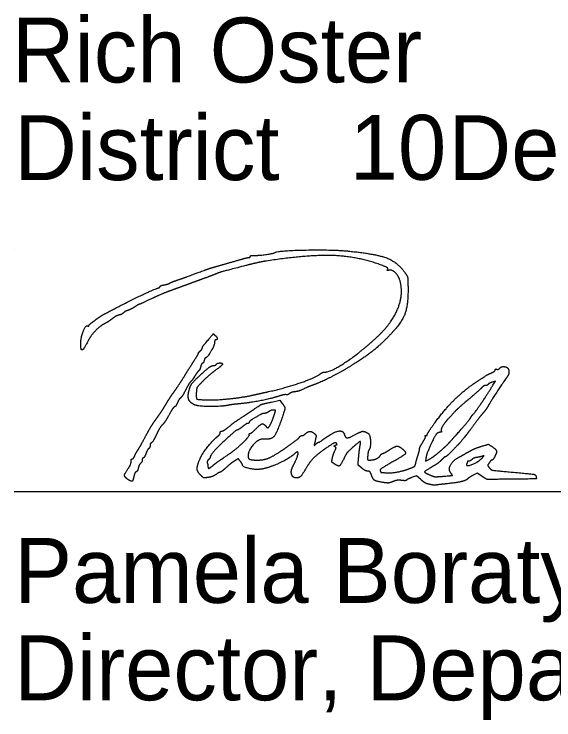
# Model space of a CAD drawing. Extents: x 0 to 34, y 0 to 22.
# Drawn here: x 24.528 to 25.691, y 7.242 to 8.764 of the extents above; entities that cross this region are included whole.
import ezdxf

# ---------------------------------------------------------------- set-up
doc = ezdxf.new("R2010")
doc.units = 0
for name, color, linetype in [('Default', 7, 'Continuous'), ('SH_Data', 7, 'Continuous'), ('SH_Text', 7, 'Continuous')]:
    doc.layers.add(name, color=color, linetype=linetype)

msp = doc.modelspace()

# ---------------------------------------------------------------- linework, layer by layer
at = {"layer": 'Default'}
for points in [[(25.5597, 7.9636), (25.5651, 7.9726), (25.5577, 7.97)], [(25.0824, 7.9275), (25.1004, 7.9315), (25.1051, 7.9253)], [(25.2773, 7.7846), (25.269, 7.791), (25.2704, 7.808)], [(25.4153, 7.8066), (25.4143, 7.8002), (25.4229, 7.8046)], [(25.4043, 7.7603), (25.3951, 7.7686), (25.3845, 7.7645)], [(25.5361, 7.7673), (25.5255, 7.7741), (25.5171, 7.7696)]]:
    msp.add_lwpolyline(points, dxfattribs=at)
for points in [[(25.0898, 8.25), (25.0966, 8.2542), (25.2136, 8.2565), (25.248, 8.2531)], [(25.248, 8.2531), (25.3072, 8.2473), (25.3548, 8.229), (25.3706, 8.206)], [(25, 8.2304), (25.0161, 8.2352), (25.031, 8.2391), (25.033, 8.2391)], [(25.033, 8.2391), (25.0351, 8.2391), (25.0368, 8.2402), (25.0368, 8.2416)], [(25.0368, 8.2416), (25.0368, 8.243), (25.0408, 8.244), (25.0458, 8.2438)], [(25.0458, 8.2438), (25.0554, 8.2435), (25.0864, 8.2479), (25.0898, 8.25)], [(25.3205, 8.2224), (25.2699, 8.2414), (25.1619, 8.2454), (25.0716, 8.2316)], [(24.9612, 8.2193), (24.9665, 8.2207), (24.9839, 8.2257), (25, 8.2304)], [(25.0272, 8.2219), (24.9762, 8.2087), (24.9719, 8.2075), (24.9612, 8.2031)], [(25.0716, 8.2316), (25.0623, 8.2302), (25.0424, 8.2258), (25.0272, 8.2219)], [(25.3328, 8.2137), (25.3338, 8.2163), (25.3303, 8.2187), (25.3205, 8.2224)], [(24.8808, 8.1909), (24.8955, 8.196), (24.9019, 8.1983), (24.9372, 8.2115)], [(24.9372, 8.2115), (24.9451, 8.2144), (24.9559, 8.2179), (24.9612, 8.2193)], [(25.3352, 8.2117), (25.3326, 8.2107), (25.3319, 8.2113), (25.3328, 8.2137)], [(25.3586, 8.1918), (25.3553, 8.2015), (25.3409, 8.2139), (25.3352, 8.2117)], [(25.3706, 8.206), (25.3755, 8.1987), (25.3764, 8.1944), (25.3768, 8.1765)], [(24.8628, 8.1837), (24.8641, 8.1847), (24.8722, 8.1879), (24.8808, 8.1909)], [(24.9384, 8.1946), (24.9285, 8.191), (24.9134, 8.1854), (24.9048, 8.1822)], [(24.9612, 8.2031), (24.9585, 8.202), (24.9483, 8.1982), (24.9384, 8.1946)], [(25.3131, 8.0706), (25.344, 8.1), (25.3679, 8.1635), (25.3586, 8.1918)], [(24.837, 8.173), (24.84, 8.1739), (24.8424, 8.1755), (24.8424, 8.1766)], [(24.8424, 8.1766), (24.8424, 8.1777), (24.8464, 8.1793), (24.8514, 8.1802)], [(24.8514, 8.1802), (24.8563, 8.1812), (24.8615, 8.1827), (24.8628, 8.1837)], [(24.9048, 8.1822), (24.8962, 8.179), (24.88, 8.1731), (24.8688, 8.1691)], [(25.3768, 8.1765), (25.3775, 8.1357), (25.3614, 8.096), (25.332, 8.0661)], [(24.7248, 8.1187), (24.755, 8.1349), (24.8286, 8.1706), (24.837, 8.173)], [(24.8688, 8.1691), (24.8576, 8.1651), (24.8372, 8.1565), (24.8236, 8.1501)], [(24.8236, 8.1501), (24.8099, 8.1436), (24.7983, 8.1383), (24.7977, 8.1383)], [(24.7877, 8.1327), (24.7828, 8.1295), (24.7761, 8.1262), (24.7729, 8.1251)], [(24.7977, 8.1383), (24.7971, 8.1383), (24.7927, 8.1358), (24.7877, 8.1327)], [(24.6888, 8.0921), (24.6888, 8.0942), (24.7142, 8.113), (24.7248, 8.1187)], [(24.754, 8.1151), (24.7505, 8.1143), (24.7438, 8.1107), (24.7392, 8.1071)], [(24.7637, 8.12), (24.7619, 8.1182), (24.7576, 8.116), (24.754, 8.1151)], [(24.7729, 8.1251), (24.7697, 8.1241), (24.7655, 8.1218), (24.7637, 8.12)], [(24.7392, 8.1071), (24.7346, 8.1035), (24.7274, 8.0988), (24.7233, 8.0967)], [(24.6716, 8.0542), (24.6717, 8.0674), (24.6823, 8.094), (24.6865, 8.0914)], [(24.6865, 8.0914), (24.6877, 8.0907), (24.6888, 8.0909), (24.6888, 8.0921)], [(24.7233, 8.0967), (24.7129, 8.0914), (24.693, 8.0705), (24.6868, 8.0584)], [(24.939, 8.0531), (24.9575, 8.0753), (24.9568, 8.0747), (24.9609, 8.0713)], [(24.9609, 8.0713), (24.9652, 8.0678), (24.9661, 8.0615), (24.9624, 8.0615)], [(25.1964, 7.9919), (25.2105, 7.9919), (25.2786, 8.0378), (25.3131, 8.0706)], [(24.673, 8.0405), (24.6722, 8.0413), (24.6716, 8.0475), (24.6716, 8.0542)], [(24.6868, 8.0584), (24.6801, 8.0455), (24.6748, 8.0386), (24.673, 8.0405)], [(24.9336, 8.0445), (24.9336, 8.0457), (24.936, 8.0496), (24.939, 8.0531)], [(24.96, 8.0564), (24.96, 8.0509), (24.9441, 8.0231), (24.9409, 8.0231)], [(24.9624, 8.0615), (24.9611, 8.0615), (24.96, 8.0592), (24.96, 8.0564)], [(25.332, 8.0661), (25.3134, 8.0472), (25.281, 8.0223), (25.2505, 8.0035)], [(24.9288, 8.0375), (24.9314, 8.0401), (24.9336, 8.0433), (24.9336, 8.0445)], [(24.916, 8.017), (24.9216, 8.0257), (24.9256, 8.0327), (24.925, 8.0327)], [(24.925, 8.0327), (24.9245, 8.0327), (24.9261, 8.0349), (24.9288, 8.0375)], [(24.9409, 8.0231), (24.9398, 8.0231), (24.9382, 8.0204), (24.9374, 8.0171)], [(24.894, 7.982), (24.9006, 7.9927), (24.9105, 8.0084), (24.916, 8.017)], [(24.9337, 8.0111), (24.9325, 8.0111), (24.9309, 8.0079), (24.93, 8.0039)], [(24.9374, 8.0171), (24.9366, 8.0138), (24.9349, 8.0111), (24.9337, 8.0111)], [(24.9576, 8.0063), (24.9601, 8.0063), (24.9628, 8.0074), (24.9636, 8.0087)], [(24.9768, 8.0091), (24.9768, 8.008), (24.97, 8.002), (24.9618, 7.9959)], [(24.9636, 8.0087), (24.9654, 8.0116), (24.9768, 8.0119), (24.9768, 8.0091)], [(24.9261, 7.9953), (24.9248, 7.9945), (24.921, 7.9894), (24.9176, 7.9839)], [(24.9252, 7.9821), (24.9409, 7.9968), (24.9536, 8.0063), (24.9576, 8.0063)], [(24.93, 8.0039), (24.9291, 8), (24.9274, 7.9961), (24.9261, 7.9953)], [(24.9618, 7.9959), (24.9535, 7.9898), (24.941, 7.979), (24.934, 7.9718)], [(25.2505, 8.0035), (25.2313, 7.9917), (25.1901, 7.9707), (25.176, 7.9656)], [(25.557, 7.9905), (25.5613, 7.9925), (25.5648, 7.9953), (25.5648, 7.9968)], [(25.5648, 7.9968), (25.5648, 7.9984), (25.5663, 7.999), (25.5682, 7.9983)], [(25.5682, 7.9983), (25.5701, 7.9976), (25.5729, 7.9985), (25.5745, 8.0004)], [(25.5745, 8.0004), (25.5761, 8.0023), (25.5798, 8.0039), (25.5827, 8.0039)], [(25.5827, 8.0039), (25.5921, 8.0039), (25.5959, 7.9879), (25.5885, 7.9789)], [(24.8722, 7.9491), (24.8776, 7.9566), (24.8874, 7.9714), (24.894, 7.982)], [(24.9038, 7.9475), (24.9066, 7.9605), (24.9127, 7.9705), (24.9252, 7.9821)], [(24.9176, 7.9839), (24.9142, 7.9784), (24.9101, 7.9728), (24.9084, 7.9715)], [(25.0764, 7.95), (25.1133, 7.9582), (25.1796, 7.9811), (25.1882, 7.9886)], [(25.1882, 7.9886), (25.1903, 7.9904), (25.1939, 7.9919), (25.1964, 7.9919)], [(25.528, 7.9735), (25.5469, 7.9858), (25.5488, 7.9869), (25.557, 7.9905)], [(25.5885, 7.9789), (25.5843, 7.9739), (25.5515, 7.9234), (25.5483, 7.9172)], [(24.9084, 7.9715), (24.9068, 7.9701), (24.9021, 7.9625), (24.8981, 7.9545)], [(24.934, 7.9718), (24.9233, 7.9609), (24.9211, 7.9572), (24.9206, 7.949)], [(25.176, 7.9656), (25.1714, 7.9639), (25.1643, 7.9611), (25.1603, 7.9594)], [(25.4334, 7.881), (25.4556, 7.9118), (25.5007, 7.9558), (25.528, 7.9735)], [(25.5169, 7.9007), (25.5197, 7.9027), (25.5479, 7.9441), (25.5597, 7.9636)], [(25.5437, 7.9631), (25.5415, 7.9631), (25.5375, 7.9607), (25.5349, 7.9577)], [(25.549, 7.9653), (25.5483, 7.9641), (25.5459, 7.9631), (25.5437, 7.9631)], [(25.5577, 7.97), (25.5537, 7.9686), (25.5498, 7.9665), (25.549, 7.9653)], [(24.8555, 7.9235), (24.8593, 7.9301), (24.8669, 7.9416), (24.8722, 7.9491)], [(24.8981, 7.9545), (24.8941, 7.9465), (24.889, 7.9385), (24.8868, 7.9367)], [(24.9192, 7.9207), (24.9087, 7.9246), (24.9016, 7.937), (24.9038, 7.9475)], [(24.9206, 7.949), (24.9197, 7.9355), (24.9238, 7.9326), (24.9444, 7.9321)], [(25.0428, 7.9425), (25.0507, 7.9443), (25.0658, 7.9476), (25.0764, 7.95)], [(25.1318, 7.9495), (25.1279, 7.949), (25.123, 7.9472), (25.121, 7.9454)], [(25.1603, 7.9594), (25.1433, 7.9519), (25.1384, 7.9502), (25.1318, 7.9495)], [(25.5349, 7.9577), (25.5322, 7.9547), (25.5197, 7.9437), (25.5072, 7.9331)], [(24.8868, 7.9367), (24.8847, 7.935), (24.8814, 7.9299), (24.8796, 7.9255)], [(24.9444, 7.9321), (24.9636, 7.9316), (25.0215, 7.9377), (25.0428, 7.9425)], [(25.0962, 7.9395), (25.0797, 7.9342), (25.0346, 7.9257), (25.0108, 7.9234)], [(25.1142, 7.9432), (25.1125, 7.9438), (25.1044, 7.9421), (25.0962, 7.9395)], [(25.121, 7.9454), (25.1189, 7.9436), (25.1158, 7.9426), (25.1142, 7.9432)], [(25.5072, 7.9331), (25.4876, 7.9166), (25.4759, 7.9052), (25.4592, 7.8863)], [(24.8425, 7.9029), (24.8458, 7.9076), (24.8517, 7.9169), (24.8555, 7.9235)], [(24.8739, 7.9175), (24.8726, 7.9175), (24.8672, 7.9096), (24.8618, 7.8999)], [(24.8796, 7.9255), (24.8777, 7.9211), (24.8752, 7.9175), (24.8739, 7.9175)], [(24.9904, 7.9208), (24.9767, 7.9178), (24.9272, 7.9177), (24.9192, 7.9207)], [(25.0108, 7.9234), (25.0025, 7.9226), (24.9933, 7.9214), (24.9904, 7.9208)], [(25.0284, 7.901), (25.06, 7.9221), (25.0614, 7.9228), (25.0824, 7.9275)], [(25.1051, 7.9253), (25.1117, 7.9166), (25.1115, 7.9117), (25.1038, 7.8891)], [(25.5483, 7.9172), (25.5466, 7.9138), (25.5427, 7.9083), (25.5397, 7.9051)], [(24.8289, 7.8837), (24.833, 7.8895), (24.8391, 7.8981), (24.8425, 7.9029)], [(24.9892, 7.8731), (25.0029, 7.8842), (25.0009, 7.8828), (25.0284, 7.901)], [(25.0678, 7.9031), (25.0656, 7.9031), (25.0612, 7.9017), (25.0581, 7.9)], [(25.0765, 7.9066), (25.074, 7.9047), (25.07, 7.9031), (25.0678, 7.9031)], [(25.075, 7.8719), (25.0768, 7.8719), (25.0866, 7.893), (25.0897, 7.9037)], [(25.0864, 7.9102), (25.0835, 7.9102), (25.0791, 7.9086), (25.0765, 7.9066)], [(25.0897, 7.9037), (25.0914, 7.9095), (25.091, 7.9103), (25.0864, 7.9102)], [(25.513, 7.8956), (25.5142, 7.8977), (25.5159, 7.9), (25.5169, 7.9007)], [(25.5397, 7.9051), (25.5367, 7.9019), (25.5278, 7.8905), (25.5199, 7.8799)], [(24.8618, 7.8999), (24.8565, 7.8903), (24.8498, 7.8803), (24.847, 7.8777)], [(25.0581, 7.9), (25.0436, 7.892), (25.0344, 7.8856), (25.0344, 7.8837)], [(25.1038, 7.8891), (25.0935, 7.8592), (25.0815, 7.8462), (25.0656, 7.8475)], [(25.4592, 7.8863), (25.4533, 7.8797), (25.4471, 7.8668), (25.4485, 7.8645)], [(25.4817, 7.8577), (25.497, 7.8749), (25.5106, 7.8912), (25.513, 7.8956)], [(24.81, 7.8515), (24.8163, 7.8634), (24.8248, 7.8779), (24.8289, 7.8837)], [(24.847, 7.8777), (24.8441, 7.8752), (24.8386, 7.8661), (24.8347, 7.8575)], [(24.9754, 7.8647), (24.9772, 7.8647), (24.9834, 7.8685), (24.9892, 7.8731)], [(25.02, 7.8743), (25.015, 7.8703), (25.01, 7.8671), (25.0088, 7.8671)], [(25.0317, 7.8815), (25.0303, 7.8815), (25.025, 7.8783), (25.02, 7.8743)], [(25.0344, 7.8837), (25.0344, 7.8825), (25.0332, 7.8815), (25.0317, 7.8815)], [(25.0488, 7.8695), (25.0589, 7.8796), (25.0654, 7.8814), (25.0704, 7.8755)], [(25.0704, 7.8755), (25.072, 7.8735), (25.0741, 7.8719), (25.075, 7.8719)], [(25.4184, 7.8577), (25.4184, 7.8591), (25.4251, 7.8696), (25.4334, 7.881)], [(25.5199, 7.8799), (25.512, 7.8692), (25.5043, 7.859), (25.5029, 7.8572)], [(24.8347, 7.8575), (24.8307, 7.8489), (24.826, 7.841), (24.8242, 7.84)], [(24.9666, 7.8535), (24.9695, 7.8559), (24.972, 7.8594), (24.972, 7.8613)], [(24.972, 7.8613), (24.972, 7.8632), (24.9735, 7.8647), (24.9754, 7.8647)], [(25.0088, 7.8671), (25.0069, 7.8671), (24.9985, 7.8598), (24.9732, 7.8366)], [(24.9883, 7.8133), (25.0039, 7.8237), (25.0344, 7.8525), (25.0344, 7.8568)], [(25.0344, 7.8568), (25.0344, 7.8585), (25.0355, 7.8599), (25.0368, 7.8599)], [(25.0368, 7.8599), (25.0381, 7.8599), (25.0435, 7.8642), (25.0488, 7.8695)], [(25.1431, 7.852), (25.1442, 7.8537), (25.1465, 7.8551), (25.1483, 7.8551)], [(25.1483, 7.8551), (25.1501, 7.8551), (25.1534, 7.8569), (25.1555, 7.859)], [(25.1555, 7.859), (25.1605, 7.864), (25.1705, 7.864), (25.1754, 7.8591)], [(25.1754, 7.8591), (25.1786, 7.8559), (25.1788, 7.8534), (25.1767, 7.8443)], [(25.1935, 7.8464), (25.2138, 7.8616), (25.2365, 7.8672), (25.2395, 7.8578)], [(25.2395, 7.8578), (25.2419, 7.8502), (25.25, 7.8501), (25.2633, 7.8574)], [(25.2633, 7.8574), (25.2752, 7.864), (25.2825, 7.8647), (25.2907, 7.8601)], [(25.2907, 7.8601), (25.2951, 7.8577), (25.2967, 7.8297), (25.2928, 7.8245)], [(25.4142, 7.8537), (25.4134, 7.8545), (25.414, 7.8551), (25.4156, 7.8551)], [(25.4156, 7.8551), (25.4171, 7.8551), (25.4184, 7.8563), (25.4184, 7.8577)], [(25.4462, 7.8623), (25.4399, 7.8623), (25.4304, 7.8471), (25.4183, 7.8179)], [(25.4485, 7.8645), (25.4493, 7.8633), (25.4482, 7.8623), (25.4462, 7.8623)], [(25.4661, 7.8403), (25.4692, 7.8438), (25.4762, 7.8517), (25.4817, 7.8577)], [(25.5029, 7.8572), (25.4896, 7.8408), (25.485, 7.8356), (25.4732, 7.8235)], [(24.7946, 7.8239), (24.7968, 7.8272), (24.8037, 7.8396), (24.81, 7.8515)], [(24.8242, 7.84), (24.8223, 7.8389), (24.8208, 7.836), (24.8208, 7.8335)], [(24.9285, 7.8052), (24.933, 7.8157), (24.9562, 7.8451), (24.9666, 7.8535)], [(25.0656, 7.8475), (25.0552, 7.8484), (25.032, 7.823), (25.032, 7.8108)], [(25.1004, 7.8202), (25.119, 7.8326), (25.1414, 7.8493), (25.1431, 7.852)], [(25.1767, 7.8443), (25.1744, 7.834), (25.1745, 7.8336), (25.1783, 7.837)], [(25.1783, 7.837), (25.1805, 7.839), (25.1832, 7.8407), (25.1841, 7.8407)], [(25.1841, 7.8407), (25.1851, 7.8407), (25.1893, 7.8433), (25.1935, 7.8464)], [(25.2734, 7.8329), (25.2752, 7.8423), (25.2726, 7.8428), (25.2633, 7.8346)], [(25.4016, 7.826), (25.4016, 7.8279), (25.4047, 7.8345), (25.4086, 7.8408)], [(25.4086, 7.8408), (25.4125, 7.8471), (25.415, 7.8529), (25.4142, 7.8537)], [(25.446, 7.8214), (25.4539, 7.8283), (25.4629, 7.8367), (25.4661, 7.8403)], [(24.8183, 7.8274), (24.8169, 7.8266), (24.8141, 7.8217), (24.812, 7.8165)], [(24.8208, 7.8335), (24.8208, 7.831), (24.8197, 7.8283), (24.8183, 7.8274)], [(24.9732, 7.8366), (24.9641, 7.8282), (24.9504, 7.8111), (24.9504, 7.8081)], [(25.202, 7.8292), (25.1823, 7.8157), (25.1651, 7.7987), (25.1568, 7.7843)], [(25.2222, 7.8386), (25.2204, 7.8404), (25.2145, 7.8377), (25.202, 7.8292)], [(25.2194, 7.831), (25.2172, 7.8323), (25.2175, 7.8333), (25.2206, 7.8344)], [(25.2187, 7.8211), (25.2215, 7.8274), (25.2217, 7.8295), (25.2194, 7.831)], [(25.2206, 7.8344), (25.2236, 7.8356), (25.224, 7.8368), (25.2222, 7.8386)], [(25.2633, 7.8346), (25.2474, 7.8205), (25.2437, 7.8161), (25.2382, 7.8048)], [(25.2704, 7.808), (25.2712, 7.8174), (25.2726, 7.8286), (25.2734, 7.8329)], [(25.2928, 7.8245), (25.2916, 7.8228), (25.2903, 7.8172), (25.2899, 7.8119)], [(25.3642, 7.8269), (25.3739, 7.8193), (25.367, 7.8113), (25.3354, 7.7936)], [(25.336, 7.8239), (25.3489, 7.8321), (25.3565, 7.8329), (25.3642, 7.8269)], [(25.3981, 7.8119), (25.4, 7.8178), (25.4016, 7.8242), (25.4016, 7.826)], [(25.506, 7.8194), (25.5139, 7.824), (25.5271, 7.8297), (25.5353, 7.8321)], [(25.5353, 7.8321), (25.5493, 7.8363), (25.5505, 7.8364), (25.5564, 7.8325)], [(25.5564, 7.8325), (25.566, 7.8262), (25.5684, 7.8188), (25.5638, 7.8098)], [(24.7824, 7.8047), (24.7838, 7.8047), (24.7862, 7.8077), (24.7877, 7.8113)], [(24.7877, 7.8113), (24.7893, 7.8149), (24.7924, 7.8206), (24.7946, 7.8239)], [(24.812, 7.8165), (24.81, 7.8113), (24.8073, 7.8071), (24.8061, 7.8071)], [(24.9568, 7.791), (24.9643, 7.7971), (24.9696, 7.8008), (24.9883, 7.8133)], [(25.032, 7.8108), (25.032, 7.8056), (25.0398, 7.8023), (25.0519, 7.8023)], [(25.0519, 7.8023), (25.065, 7.8023), (25.0841, 7.8094), (25.1004, 7.8202)], [(25.1324, 7.8161), (25.1228, 7.8069), (25.084, 7.7881), (25.0656, 7.7837)], [(25.1294, 7.7903), (25.1335, 7.798), (25.14, 7.8143), (25.14, 7.817)], [(25.14, 7.817), (25.14, 7.8201), (25.136, 7.8196), (25.1324, 7.8161)], [(25.2136, 7.8055), (25.2144, 7.8097), (25.2166, 7.8167), (25.2187, 7.8211)], [(25.2899, 7.8119), (25.2894, 7.8043), (25.2901, 7.8023), (25.2932, 7.8023)], [(25.2932, 7.8023), (25.3016, 7.8023), (25.3136, 7.8071), (25.3168, 7.8118)], [(25.3168, 7.8118), (25.3187, 7.8145), (25.3212, 7.8167), (25.3224, 7.8167)], [(25.3224, 7.8167), (25.3236, 7.8167), (25.3297, 7.8199), (25.336, 7.8239)], [(25.3933, 7.7948), (25.394, 7.7983), (25.3961, 7.806), (25.3981, 7.8119)], [(25.4183, 7.8179), (25.4172, 7.8153), (25.4159, 7.8102), (25.4153, 7.8066)], [(25.4229, 7.8046), (25.4277, 7.807), (25.4381, 7.8146), (25.446, 7.8214)], [(25.4576, 7.8095), (25.4565, 7.8095), (25.4526, 7.8064), (25.449, 7.8025)], [(25.4732, 7.8235), (25.4657, 7.8158), (25.4586, 7.8095), (25.4576, 7.8095)], [(25.4864, 7.8084), (25.4893, 7.81), (25.4981, 7.8149), (25.506, 7.8194)], [(25.5372, 7.8107), (25.5345, 7.8098), (25.5292, 7.8085), (25.5254, 7.808)], [(25.5348, 7.8052), (25.5403, 7.8108), (25.5408, 7.8121), (25.5372, 7.8107)], [(25.5638, 7.8098), (25.5616, 7.8057), (25.5589, 7.8023), (25.5578, 7.8023)], [(24.7742, 7.7848), (24.7774, 7.7895), (24.78, 7.7959), (24.78, 7.799)], [(24.78, 7.799), (24.78, 7.8022), (24.7811, 7.8047), (24.7824, 7.8047)], [(24.8005, 7.7952), (24.7986, 7.7937), (24.7964, 7.7891), (24.7955, 7.7852)], [(24.804, 7.8026), (24.804, 7.8001), (24.8024, 7.7968), (24.8005, 7.7952)], [(24.8061, 7.8071), (24.8049, 7.8071), (24.804, 7.8051), (24.804, 7.8026)], [(24.9302, 7.7695), (24.9225, 7.7771), (24.9219, 7.79), (24.9285, 7.8052)], [(24.9466, 7.803), (24.9446, 7.801), (24.9435, 7.7977), (24.9442, 7.7958)], [(24.9442, 7.7958), (24.945, 7.7939), (24.9456, 7.7908), (24.9456, 7.7889)], [(24.9504, 7.8081), (24.9504, 7.8074), (24.9487, 7.8051), (24.9466, 7.803)], [(25.0041, 7.8011), (24.9959, 7.7957), (24.9933, 7.7937), (24.9821, 7.7837)], [(25.0154, 7.7997), (25.0109, 7.8055), (25.0108, 7.8056), (25.0041, 7.8011)], [(25.0199, 7.7924), (25.0199, 7.7932), (25.0179, 7.7965), (25.0154, 7.7997)], [(25.2182, 7.794), (25.2132, 7.7972), (25.2124, 7.7992), (25.2136, 7.8055)], [(25.2382, 7.8048), (25.2315, 7.7911), (25.2267, 7.7884), (25.2182, 7.794)], [(25.3806, 7.7842), (25.3894, 7.7876), (25.3923, 7.79), (25.3933, 7.7948)], [(25.449, 7.8025), (25.4454, 7.7987), (25.4373, 7.7926), (25.431, 7.789)], [(25.4694, 7.774), (25.4633, 7.7815), (25.4731, 7.8012), (25.4864, 7.8084)], [(25.5033, 7.7942), (25.5008, 7.7876), (25.5263, 7.7966), (25.5348, 7.8052)], [(25.5048, 7.7989), (25.5048, 7.7983), (25.5041, 7.7962), (25.5033, 7.7942)], [(25.5076, 7.7999), (25.506, 7.7999), (25.5048, 7.7994), (25.5048, 7.7989)], [(25.5144, 7.8035), (25.5122, 7.8015), (25.5091, 7.7999), (25.5076, 7.7999)], [(25.5254, 7.808), (25.5215, 7.8075), (25.5166, 7.8055), (25.5144, 7.8035)], [(25.5519, 7.7965), (25.5484, 7.7911), (25.5484, 7.7903), (25.5523, 7.7855)], [(25.5578, 7.8023), (25.5567, 7.8023), (25.554, 7.7997), (25.5519, 7.7965)], [(24.7725, 7.7611), (24.7655, 7.766), (24.7659, 7.7727), (24.7742, 7.7848)], [(24.7955, 7.7852), (24.7946, 7.7812), (24.7925, 7.7774), (24.7908, 7.7768)], [(24.9456, 7.7889), (24.9456, 7.784), (24.949, 7.7847), (24.9568, 7.791)], [(24.9821, 7.7837), (24.9773, 7.7794), (24.9725, 7.7759), (24.9714, 7.7759)], [(25.0656, 7.7837), (25.0527, 7.7806), (25.0201, 7.7868), (25.0199, 7.7924)], [(25.1361, 7.7639), (25.1277, 7.7639), (25.1237, 7.7797), (25.1294, 7.7903)], [(25.1568, 7.7843), (25.1486, 7.7702), (25.1422, 7.7639), (25.1361, 7.7639)], [(25.2903, 7.7783), (25.2877, 7.7783), (25.2819, 7.7812), (25.2773, 7.7846)], [(25.3354, 7.7936), (25.3222, 7.7862), (25.316, 7.7814), (25.3168, 7.7792)], [(25.3168, 7.7792), (25.3181, 7.7758), (25.3188, 7.7756), (25.3308, 7.7749)], [(25.3308, 7.7749), (25.3413, 7.7742), (25.3674, 7.7791), (25.3806, 7.7842)], [(25.431, 7.789), (25.4131, 7.7785), (25.412, 7.7753), (25.425, 7.7697)], [(25.5523, 7.7855), (25.5559, 7.781), (25.5609, 7.78), (25.5948, 7.7769)], [(24.7862, 7.7676), (24.7843, 7.7578), (24.7801, 7.7558), (24.7725, 7.7611)], [(24.7908, 7.7768), (24.7891, 7.7761), (24.787, 7.772), (24.7862, 7.7676)], [(24.9464, 7.7649), (24.9377, 7.7635), (24.9355, 7.7642), (24.9302, 7.7695)], [(24.9629, 7.7712), (24.9593, 7.7686), (24.9519, 7.7657), (24.9464, 7.7649)], [(24.9714, 7.7759), (24.9703, 7.7759), (24.9665, 7.7738), (24.9629, 7.7712)], [(25.2978, 7.7705), (25.296, 7.7757), (25.2934, 7.7783), (25.2903, 7.7783)], [(25.3232, 7.754), (25.3082, 7.7564), (25.3013, 7.7608), (25.2978, 7.7705)], [(25.3845, 7.7645), (25.3787, 7.7623), (25.3737, 7.7597), (25.3733, 7.7588)], [(25.425, 7.7697), (25.4318, 7.7668), (25.4383, 7.7662), (25.4518, 7.7673)], [(25.4518, 7.7673), (25.4713, 7.7688), (25.4731, 7.7695), (25.4694, 7.774)], [(25.5171, 7.7696), (25.5125, 7.7671), (25.5072, 7.7636), (25.5054, 7.7618)], [(25.5828, 7.7609), (25.5471, 7.7605), (25.5467, 7.7606), (25.5361, 7.7673)], [(25.6531, 7.766), (25.6539, 7.7618), (25.6519, 7.7616), (25.5828, 7.7609)], [(25.5948, 7.7769), (25.6439, 7.7723), (25.6521, 7.7708), (25.6531, 7.766)], [(25.3443, 7.7559), (25.3373, 7.7531), (25.3318, 7.7526), (25.3232, 7.754)], [(25.3632, 7.7584), (25.3574, 7.7592), (25.3501, 7.7582), (25.3443, 7.7559)], [(25.3733, 7.7588), (25.3729, 7.7579), (25.3683, 7.7578), (25.3632, 7.7584)], [(25.4189, 7.7509), (25.4159, 7.7515), (25.4093, 7.7558), (25.4043, 7.7603)], [(25.4292, 7.7487), (25.4265, 7.7492), (25.4219, 7.7502), (25.4189, 7.7509)], [(25.4376, 7.7484), (25.4356, 7.748), (25.4318, 7.7482), (25.4292, 7.7487)], [(25.4568, 7.7508), (25.4482, 7.7499), (25.4396, 7.7488), (25.4376, 7.7484)], [(25.5054, 7.7618), (25.5017, 7.758), (25.4802, 7.7532), (25.4568, 7.7508)]]:
    msp.add_open_spline(points, degree=2, dxfattribs=at)
at = {"layer": 'SH_Data'}
for p, q in [((24.5279, 8.2564), (24.5279, 8.2564)), ((24.5279, 7.7342), (28.0279, 7.7342))]:
    msp.add_line(p, q, dxfattribs=at)

# ---------------------------------------------------------------- texts
at = {"layer": 'SH_Text'}
for s, p in [('Rich Oster', (24.5228, 8.6168)), ('District       Deputy Director', (24.5279, 8.4062)), ('              10', (24.5228, 8.4068)), ('Pamela Boratyn', (24.5279, 7.4942)), ('Director, Department of Transportation', (24.5279, 7.2842))]:
    msp.add_text(s, height=0.14, dxfattribs=at).set_placement(p)

doc.saveas('drawing.dxf')
